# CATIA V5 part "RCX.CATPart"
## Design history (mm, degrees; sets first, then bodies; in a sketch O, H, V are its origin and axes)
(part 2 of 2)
Body10, material "Purple Grey"
  Sketch38 on face of Pocket2 from Sketch3.L3, origin (0, 0, 350), H (1, 0, 0), V (0, 1, 0)
    line L1 (237, 162) -> (-237, 162)
    line L2 (237, 320) -> (237, 162)
    line L3 (-237, 320) -> (237, 320)
    line L4 (-237, 162) -> (-237, 320)
    reference projected line E1 (-245, 320) -> (-309.2857, 320) from edge [face of Pocket2 from Sketch3.L3 | end face of Pocket3]
    distance L1 L3 = 158
    distance L2 L4 = 474
    coincidence: L3 E1
    symmetry: L2 L4 V
  Pad12: profile Sketch38, direction (0, 0, -1), length 30
  Sketch39 on start face of Pad3, origin (0, 0, 350), H (1, 0, 0), V (0, 1, 0)
    circle A1 centre (197.5, 280.5) radius 24.5
    point P1 (197.5, 280.5)
    reference projected line E1 (237, 162) -> (237, 320) from edge [face of Pocket2 from Sketch3.L3 | face of Pocket6 from Sketch7.L6]
    reference projected line E2 (237, 320) -> (-237, 320) from edge [face of Pocket2 from Sketch3.L3 | face of Pocket6 from Sketch7.L7]
    radius A1 = 24.5
    distance P1 E1 = 39.5
    distance P1 E2 = 39.5
  Pad13: profile Sketch39, direction (0, 0, 1), length 17.2
  RectPattern3: of Pad13, direction 1 instances 6, spacing 79, along start face of Pad12 reversed, direction 2 instances 2, spacing 79, along start face of Pad12 reversed
  Sketch40 on start face of Pad3, origin (0, 0, 350), H (1, 0, 0), V (0, 1, 0)
    point P1 (79, 162)
    point P2 (79, 320)
    line L1 (79, 320) -> (79, 162)
    reference projected line E1 (237, 162) -> (237, 320) from edge [face of Pocket2 from Sketch3.L3 | face of Pocket6 from Sketch7.L6]
    reference projected line E2 (237, 320) -> (-237, 320) from edge [face of Pocket2 from Sketch3.L3 | face of Pocket6 from Sketch7.L7]
    reference projected line E3 (-237, 162) -> (237, 162) from edge [face of Pocket2 from Sketch3.L3 | face of Pocket6 from Sketch7.L5]
    point P3 (-79, 162)
    point P4 (-79, 320)
    line L2 (-79, 320) -> (-79, 162)
    reference projected line E4 (-237, 320) -> (-237, 162) from edge [face of Pocket2 from Sketch3.L3 | face of Pocket6 from Sketch7.L8]
    reference projected line E5 (237, 320) -> (-237, 320) from edge [face of Pocket2 from Sketch3.L3 | face of Pocket6 from Sketch7.L7]
    reference projected line E6 (-237, 162) -> (237, 162) from edge [face of Pocket2 from Sketch3.L3 | face of Pocket6 from Sketch7.L5]
    distance L1 E1 = 158
    distance L2 E4 = 158
    coincidence: P2 E2, P1 E3, P4 E5, P3 E6
  Pocket27: profile Sketch40, direction (0, 0, -1), length 5, thin wall 1, second thickness 1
